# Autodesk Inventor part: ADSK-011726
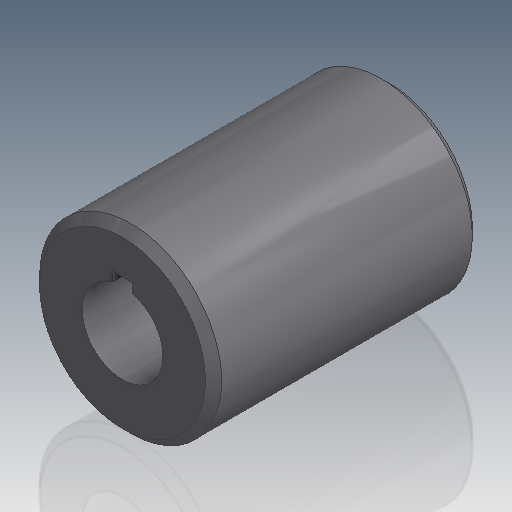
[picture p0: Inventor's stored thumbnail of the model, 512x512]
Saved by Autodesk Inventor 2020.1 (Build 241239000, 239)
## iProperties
Created: 1999-11
Part Number: ADSK-011726
Material: Acier doux
Description: COUPLING,SHAFT,0.750X0.75
Document SubType Name: Modeling
Designer: kcovelli
Density: 7.86 g/cm^3
Appearance: Metal-Steel(Polish)
Mass: 652.305 g
Surface Area: 159.696 cm^2
Volume: 82.9905 cm^3
Control State: 0
Checked Out: False
Last Check In By: kcovelli
Master: False
Shininess: 0.0
Length Units: 11269
Angle Units: 11279
Time Units: 11290
Mass Units: 11283
Length Display Precision: 3
Angle Display Precision: 2
Compacted: True
Dimensions: 45x45x66 mm
Mass: 0,652 kg
DocNumber: ADSK-011726.ipt
Folder: 01 - Themengebiete\Simplification\01 - Packaging machine\
VDS_Category: 3D Komponenten
Density: 0.0
Volumn: 0.0
Area: 0.0
PropertySet Name: Model Information
Author: kcovelli
Revision Number: -
Title: clutch
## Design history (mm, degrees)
node "Solide1"
  node "Extrusion1" dims "d2" = 66, "d3" = 0
sketch "Sketch1"
  geometry: C1 r 22.5 at (0, 0); C2 r 10 at (0, 0)
  constraints: 2 centre point, 1 coincident, 1 other
  dimensions: "d0" = 45 diameter of C1; "d1" = 20 diameter of C2
chamfer "Fase1" distance "d5" = 2; stored, may be unused: second distance "d6" = 2, angle "d7" = 45 deg
sketch "Skizze2"
  geometry: L1 (-2.5, 9.682)-(-2.5, 12); L2 (-2.5, 12)-(2.5, 12); L3 (2.5, 12)-(2.5, 9.682); A1 r 10 centre (0, 0) between (-2.5, 9.682) and (2.5, 9.682) reference; 2 further points
  constraints: 6 end point, 2 perpendicular, 2 point on circle, 1 midpoint, 1 vertical, 1 vertical alignment
  dimensions: "d8" = 5 distance of L1.end L2.end; "d9" = 12 distance from line of point (0, 0) L2
extrude "Extrusion2" cut sketch "Skizze2" extent not by distance; stored distance "d10" = 0; taper "d11" = 0 deg
node "Corps solides"
node "Corps surfaciques"
